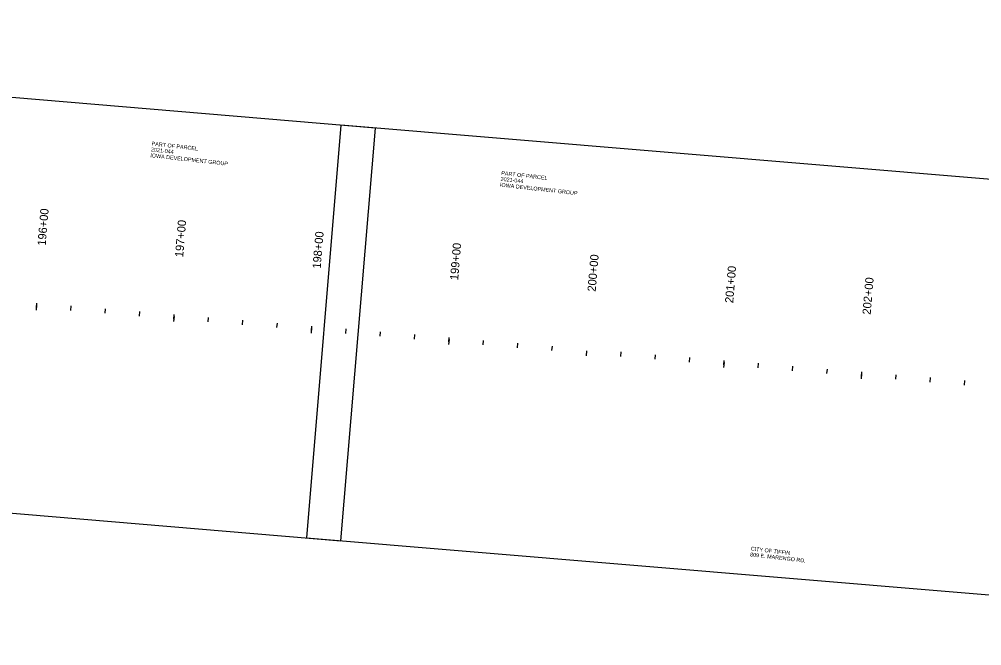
# Model space of a CAD drawing. Extents: x 20499788 to 20505371, y 7953467 to 7954209.
# Drawn here: x 20503290 to 20503988, y 7953516 to 7953970 of the extents above; entities that cross this region are included whole.
import ezdxf

# ---------------------------------------------------------------- set-up
doc = ezdxf.new("R2010")
doc.units = 0
for name, color, linetype in [('NamedBoundary', 7, 'Continuous'), ('Text', 7, 'Continuous'), ('TextAlignmentLrg', 7, 'Continuous'), ('TextAlignmentSml', 7, 'Continuous')]:
    doc.layers.add(name, color=color, linetype=linetype)

msp = doc.modelspace()

# ---------------------------------------------------------------- linework, layer by layer
at = {"layer": 'NamedBoundary'}
for points in [[(20502611.39, 7953970.38), (20502586.22, 7953671.43), (20503523.4, 7953592.51), (20503548.57, 7953891.46)], [(20503523.55, 7953893.55), (20503498.6, 7953594.59), (20504435.84, 7953516.39), (20504460.79, 7953815.35)]]:
    msp.add_lwpolyline(points, close=True, dxfattribs=at)
at = {"layer": 'TextAlignmentLrg'}
for p, q in [((20503302.8, 7953761.46), (20503303.07, 7953764.72)), ((20503402.45, 7953753.14), (20503402.72, 7953756.4)), ((20503502.11, 7953744.82), (20503502.38, 7953748.09)), ((20503601.76, 7953736.51), (20503602.03, 7953739.77)), ((20503701.57, 7953730.02), (20503701.26, 7953726.36)), ((20503801.07, 7953719.87), (20503801.34, 7953723.14)), ((20503900.72, 7953711.56), (20503900.99, 7953714.82))]:
    msp.add_line(p, q, dxfattribs=at)
at = {"layer": 'TextAlignmentSml'}
for p, q in [((20503302.95, 7953763.29), (20503302.65, 7953759.63)), ((20503327.71, 7953759.38), (20503327.98, 7953762.64)), ((20503352.63, 7953757.3), (20503352.9, 7953760.56)), ((20503377.54, 7953755.22), (20503377.81, 7953758.48)), ((20503402.61, 7953754.97), (20503402.3, 7953751.31)), ((20503427.37, 7953751.06), (20503427.64, 7953754.32)), ((20503452.28, 7953748.98), (20503452.55, 7953752.25)), ((20503477.19, 7953746.9), (20503477.46, 7953750.17)), ((20503502.26, 7953746.65), (20503501.95, 7953742.99)), ((20503527.02, 7953742.74), (20503527.29, 7953746.01)), ((20503551.93, 7953740.66), (20503552.21, 7953743.93)), ((20503576.85, 7953738.59), (20503577.12, 7953741.85)), ((20503601.91, 7953738.34), (20503601.61, 7953734.68)), ((20503626.67, 7953734.43), (20503626.95, 7953737.69)), ((20503651.59, 7953732.35), (20503651.86, 7953735.61)), ((20503676.5, 7953730.27), (20503676.77, 7953733.53)), ((20503701.57, 7953730.02), (20503701.26, 7953726.36)), ((20503726.33, 7953726.11), (20503726.6, 7953729.38)), ((20503751.24, 7953724.03), (20503751.51, 7953727.3)), ((20503776.15, 7953721.95), (20503776.43, 7953725.22)), ((20503801.22, 7953721.7), (20503800.91, 7953718.04)), ((20503825.98, 7953717.79), (20503826.25, 7953721.06)), ((20503850.89, 7953715.72), (20503851.17, 7953718.98)), ((20503875.81, 7953713.64), (20503876.08, 7953716.9)), ((20503900.87, 7953713.39), (20503900.57, 7953709.73)), ((20503925.63, 7953709.48), (20503925.91, 7953712.74)), ((20503950.55, 7953707.4), (20503950.82, 7953710.66)), ((20503975.46, 7953705.32), (20503975.73, 7953708.58))]:
    msp.add_line(p, q, dxfattribs=at)

# ---------------------------------------------------------------- texts
at = {"layer": 'Text'}
for s, height, rotation, p in [('2021-044', 2.835, 353.65909, (20503385.75, 7953874.69)), ('PART OF PARCEL', 2.8346, 353.65909, (20503386.22, 7953878.92)), ('IOWA DEVELOPMENT GROUP', 2.8346, 353.65909, (20503385.29, 7953870.47)), ('PART OF PARCEL', 2.8346, 353.65909, (20503639.6, 7953857.58)), ('IOWA DEVELOPMENT GROUP', 2.8346, 353.65909, (20503638.66, 7953849.12)), ('2021-044', 2.835, 353.65909, (20503639.13, 7953853.35)), ('CITY OF TIFFIN', 2.8346, 353.49015, (20503820.48, 7953585.42)), ('809 E. MARENGO RD.', 2.8346, 353.49015, (20503819.99, 7953581.2))]:
    msp.add_text(s, height=height, rotation=rotation, dxfattribs=at).set_placement(p)
at = {"layer": 'TextAlignmentLrg'}
msp.add_text('200+00', height=6.012, rotation=85.22957, dxfattribs=at).set_placement((20503708.15, 7953772.78))
at = {"layer": 'TextAlignmentSml'}
for s, p in [('196+00', (20503309.54, 7953806.05)), ('197+00', (20503409.19, 7953797.73)), ('198+00', (20503508.84, 7953789.42)), ('199+00', (20503608.5, 7953781.1)), ('200+00', (20503708.15, 7953772.78)), ('201+00', (20503807.8, 7953764.47)), ('202+00', (20503907.46, 7953756.15))]:
    msp.add_text(s, height=6.012, rotation=85.22957, dxfattribs=at).set_placement(p)

doc.saveas('drawing.dxf')
